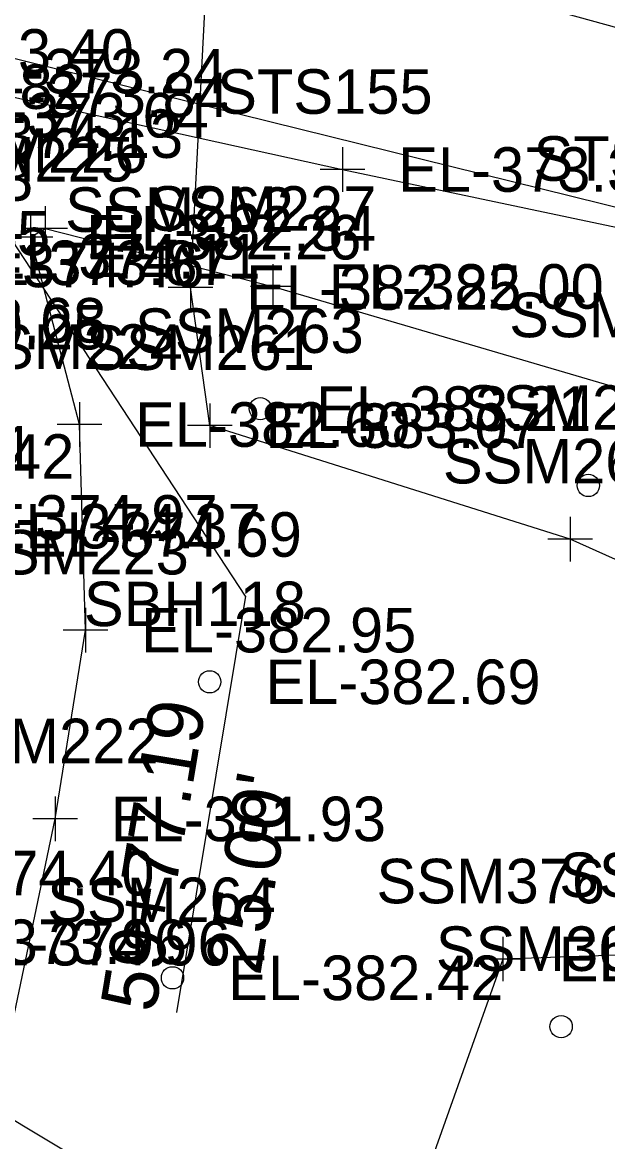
# Model space of a CAD drawing. Extents: x 1189978 to 1314812, y 571533 to 629339.
# Drawn here: x 1217620.1 to 1217672.6, y 621600.5 to 621701 of the extents above; entities that cross this region are included whole.
import ezdxf

# ---------------------------------------------------------------- set-up
doc = ezdxf.new("R2010")
doc.units = 0
for name, color, linetype in [('SURVEY - DRAINAGE - Bridge Hydraulic Data - Points - Elevations', 7, 'Continuous'), ('SURVEY - DRAINAGE - Bridge Hydraulic Data - Points - Numbers', 7, 'Continuous'), ('SURVEY - DRAINAGE - Bridge Hydraulic Data with Text', 7, 'Continuous'), ('SURVEY - DRAINAGE - Natural Features', 7, 'Continuous'), ('SURVEY - DRAINAGE - Pipes and Culverts', 7, 'Continuous'), ('SURVEY - DTM - Breaklines', 7, 'Continuous'), ('SURVEY - DTM - Breaklines - Points - Elevations', 7, 'Continuous'), ('SURVEY - DTM - Breaklines - Points - Locators', 7, 'Continuous'), ('SURVEY - DTM - Breaklines - Points - Numbers', 7, 'Continuous'), ('SURVEY - DTM - Spot Points - Elevations', 7, 'Continuous'), ('SURVEY - DTM - Spot Points - Locators', 7, 'Continuous'), ('SURVEY - DTM - Spot Points - Point Numbers', 7, 'Continuous'), ('SURVEY - PROPERTY - Property Lines', 7, 'Continuous'), ('SURVEY - PROPERTY - Station and Offset Flags', 7, 'Continuous'), ('SURVEY - VEGETATION - Features - Points - Elevations', 7, 'Continuous'), ('SURVEY - VEGETATION - Features - Points - Locators', 7, 'Continuous'), ('SURVEY - VEGETATION - Features - Points - Numbers', 7, 'Continuous'), ('SURVEY - VEGETATION - Features with Text', 7, 'Continuous')]:
    doc.layers.add(name, color=color, linetype=linetype)

msp = doc.modelspace()

# ---------------------------------------------------------------- linework, layer by layer
at = {"layer": 'SURVEY - DRAINAGE - Bridge Hydraulic Data with Text'}
for p, q in [((1217648.86, 621689.75), (1217648.86, 621685.75)), ((1217650.86, 621687.75), (1217646.86, 621687.75)), ((1217620.87, 621683.67), (1217620.87, 621679.67)), ((1217622.2, 621684.46), (1217622.2, 621680.46)), ((1217624.2, 621682.46), (1217620.2, 621682.46)), ((1217622.87, 621681.67), (1217618.87, 621681.67)), ((1217642.62, 621679.25), (1217642.62, 621675.25)), ((1217644.62, 621677.25), (1217640.62, 621677.25)), ((1217625.26, 621666.85), (1217625.26, 621662.85)), ((1217627.26, 621664.85), (1217623.26, 621664.85)), ((1217625.8, 621648.39), (1217625.8, 621644.39)), ((1217627.8, 621646.39), (1217623.8, 621646.39)), ((1217623.08, 621631.44), (1217623.08, 621627.44)), ((1217625.08, 621629.44), (1217621.08, 621629.44))]:
    msp.add_line(p, q, dxfattribs=at)
for points in [[(1217608.75, 621696.58), (1217648.86, 621687.75), (1217677.35, 621681.74), (1217732.6, 621657.47), (1217781.29, 621629.61), (1217836.19, 621612.25), (1217873.97, 621607.18), (1217947.65, 621606.21), (1218006.33, 621594.8), (1218055.31, 621583.64), (1218102.03, 621575.33), (1218143.8, 621568.44), (1218175.72, 621558.82)], [(1217620.87, 621681.67), (1217622.2, 621682.46), (1217642.62, 621677.25), (1217675.1, 621667.69), (1217729.16, 621644.15), (1217773.26, 621620.9), (1217815.41, 621607.07), (1217868.64, 621590.01), (1217924.4, 621592.51), (1217974.68, 621583.83), (1218029.18, 621580.33), (1218078.58, 621559.01), (1218129.76, 621551.77), (1218165.8, 621544.45)], [(1217505.54, 621026.79), (1217510.58, 621028.06), (1217516.48, 621028.53), (1217518.24, 621034.42), (1217525.77, 621071.02), (1217531.12, 621100.75), (1217543.76, 621178.47), (1217557.61, 621268.24), (1217565, 621315.17), (1217570.43, 621349.89), (1217572.63, 621390.62), (1217580.88, 621434.75), (1217592.39, 621481.3), (1217594.39, 621494.68), (1217597.98, 621511.62), (1217601.47, 621549.78), (1217613.22, 621582.3), (1217623.08, 621629.44), (1217625.8, 621646.39), (1217625.26, 621664.85), (1217620.87, 621681.67)]]:
    msp.add_lwpolyline(points, dxfattribs=at)
at = {"layer": 'SURVEY - DRAINAGE - Natural Features'}
msp.add_lwpolyline([(1217597.92, 621711.33), (1217604.68, 621710.65), (1217655.29, 621705.53), (1217679.89, 621698.73), (1217740.8, 621672.97), (1217788.76, 621648.92), (1217842.88, 621634.67), (1217893, 621624.41), (1217946.99, 621626.51), (1218003.43, 621612.97), (1218049.35, 621603.62), (1218106.32, 621591.17), (1218155.43, 621579.99), (1218184.56, 621577.09)], dxfattribs=at)
at = {"layer": 'SURVEY - DRAINAGE - Pipes and Culverts'}
msp.add_line((1217655.99, 621580.4), (1217606.77, 621609.94), dxfattribs=at)
at = {"layer": 'SURVEY - DTM - Breaklines'}
msp.add_lwpolyline([(1217652.9, 621587.7), (1217651.43, 621582.83), (1217643.26, 621546.04), (1217642.15, 621538.34), (1217648.55, 621531.36), (1217656.64, 621530.3), (1217674, 621546.86), (1217683.49, 621555.46), (1217690.06, 621576.59), (1217691.54, 621598.37), (1217679.54, 621617.42), (1217663.26, 621616.86), (1217652.9, 621587.7)], dxfattribs=at)
at = {"layer": 'SURVEY - DTM - Breaklines - Points - Locators'}
for p, q in [((1217663.26, 621618.86), (1217663.26, 621614.86)), ((1217665.26, 621616.86), (1217661.26, 621616.86))]:
    msp.add_line(p, q, dxfattribs=at)
at = {"layer": 'SURVEY - DTM - Spot Points - Locators'}
for centre in [(1217641.49, 621666.28), (1217670.92, 621659.38), (1217636.95, 621641.75), (1217633.61, 621615.17), (1217668.48, 621610.79)]:
    msp.add_circle(centre, 1, dxfattribs=at)
at = {"layer": 'SURVEY - PROPERTY - Property Lines'}
msp.add_line((1217606.4, 621700.95), (1218832.82, 621397.44), dxfattribs=at)
at = {"layer": 'SURVEY - PROPERTY - Station and Offset Flags'}
msp.add_line((1217640.15, 621649.45), (1217633.97, 621612.06), dxfattribs=at)
msp.add_lwpolyline([(1217640.15, 621649.45), (1217606.4, 621700.95)], dxfattribs=at)
at = {"layer": 'SURVEY - VEGETATION - Features - Points - Locators'}
for p, q in [((1217635.22, 621679.15), (1217635.22, 621675.15)), ((1217637.22, 621677.15), (1217633.22, 621677.15)), ((1217636.96, 621666.75), (1217636.96, 621662.75)), ((1217638.96, 621664.75), (1217634.96, 621664.75)), ((1217669.28, 621656.56), (1217669.28, 621652.56)), ((1217671.28, 621654.56), (1217667.28, 621654.56))]:
    msp.add_line(p, q, dxfattribs=at)
at = {"layer": 'SURVEY - VEGETATION - Features with Text'}
for points in [[(1217635.22, 621677.15), (1217638.44, 621739.02), (1217645.2, 621755.16), (1217657.66, 621755.11), (1217696.15, 621736.61), (1217739.97, 621716.31), (1217783.32, 621708.86), (1217822.96, 621695.3), (1217862.84, 621685.05), (1217908.72, 621679.47), (1217951.79, 621669.62), (1217991.8, 621657.05), (1218033.03, 621649.12), (1218078.72, 621641.96), (1218126.57, 621635.34), (1218178.05, 621621.05)], [(1218164.35, 621532.61), (1218126.36, 621537.58), (1218076.43, 621544.76), (1218024.24, 621555.32), (1217973.55, 621564.98), (1217919.77, 621572.71), (1217865.16, 621580.88), (1217811.45, 621595.34), (1217767.54, 621609.78), (1217723.9, 621630.04), (1217669.28, 621654.56), (1217636.96, 621664.75), (1217635.22, 621677.15)]]:
    msp.add_lwpolyline(points, dxfattribs=at)

# ---------------------------------------------------------------- texts
at = {"layer": 'SURVEY - DRAINAGE - Bridge Hydraulic Data - Points - Elevations'}
for s, p in [('EL-373.40', (1217605.47, 621696.35)), ('EL-373.24', (1217613.75, 621694.58)), ('EL-373.33', (1217653.86, 621685.75)), ('EL-382.34', (1217627.2, 621680.46)), ('EL-382.00', (1217647.62, 621675.25))]:
    msp.add_text(s, height=4, dxfattribs=at).set_placement(p)
at = {"layer": 'SURVEY - DRAINAGE - Bridge Hydraulic Data - Points - Numbers'}
for s, p in [('STS155', (1217637.62, 621692.75)), ('SSM226', (1217610.85, 621687.46)), ('STS156', (1217666, 621686.74)), ('SSM227', (1217631.38, 621682.25)), ('SSM228', (1217663.82, 621672.69))]:
    msp.add_text(s, height=4, dxfattribs=at).set_placement(p)
at = {"layer": 'SURVEY - DTM - Breaklines - Points - Elevations'}
for s, p in [('EL-373.84', (1217613.98, 621692.45)), ('EL-373.64', (1217612.18, 621690.62)), ('EL-374.13', (1217609.88, 621688.79)), ('EL-382.26', (1217625.87, 621679.67)), ('EL-374.11', (1217616.84, 621677.95)), ('EL-374.46', (1217611.79, 621677.18)), ('EL-373.87', (1217614.15, 621677.37)), ('EL-379.25', (1217602.98, 621671.59)), ('EL-378.68', (1217602.99, 621672.21)), ('EL-382.60', (1217630.26, 621662.85)), ('EL-374.97', (1217612.97, 621654.51)), ('EL-374.37', (1217616.84, 621653.72)), ('EL-374.69', (1217620.53, 621652.98)), ('EL-382.95', (1217630.8, 621644.39)), ('EL-381.93', (1217628.08, 621627.44)), ('EL-374.40', (1217607.31, 621622.58)), ('EL-373.96', (1217610.23, 621616.41)), ('EL-374.96', (1217614.15, 621616.28)), ('EL-382.28', (1217668.26, 621614.86))]:
    msp.add_text(s, height=4, dxfattribs=at).set_placement(p)
at = {"layer": 'SURVEY - DTM - Breaklines - Points - Numbers'}
for s, p in [('SSM225', (1217609.63, 621686.67)), ('SSM343', (1217600.6, 621684.95)), ('SSM224', (1217614.02, 621669.85)), ('SSM341', (1217600.76, 621660.72)), ('SSM342', (1217604.29, 621659.98)), ('SSM223', (1217614.56, 621651.39)), ('SSM222', (1217611.84, 621634.44)), ('SSM375', (1217668.3, 621622.42)), ('SSM376', (1217651.91, 621621.86))]:
    msp.add_text(s, height=4, dxfattribs=at).set_placement(p)
at = {"layer": 'SURVEY - DTM - Spot Points - Elevations'}
for s, p in [('EL-374.82', (1217601.15, 621693.19)), ('EL-377.45', (1217597.95, 621680.03)), ('EL-383.21', (1217646.49, 621664.28)), ('EL-382.69', (1217641.95, 621639.75)), ('EL-382.42', (1217638.61, 621613.17))]:
    msp.add_text(s, height=4, dxfattribs=at).set_placement(p)
at = {"layer": 'SURVEY - DTM - Spot Points - Point Numbers'}
for s, p in [('SSM263', (1217630.25, 621671.28)), ('SSM259', (1217659.66, 621664.38)), ('SBH118', (1217625.66, 621646.75)), ('SSM264', (1217622.37, 621620.17)), ('SSM364', (1217657.24, 621615.79))]:
    msp.add_text(s, height=4, dxfattribs=at).set_placement(p)
at = {"layer": 'SURVEY - PROPERTY - Station and Offset Flags'}
for s, p in [('59+77.19', (1217632.05, 621611.94)), ("25.00'", (1217641.47, 621615.27))]:
    msp.add_text(s, height=5, rotation=80.6236, dxfattribs=at).set_placement(p)
at = {"layer": 'SURVEY - VEGETATION - Features - Points - Elevations'}
for s, p in [('EL-382.25', (1217640.22, 621675.15)), ('EL-383.07', (1217641.96, 621662.75))]:
    msp.add_text(s, height=4, dxfattribs=at).set_placement(p)
at = {"layer": 'SURVEY - VEGETATION - Features - Points - Numbers'}
for s, p in [('SSM262', (1217623.98, 621682.15)), ('SSM261', (1217625.88, 621669.75)), ('SSM260', (1217657.87, 621659.56))]:
    msp.add_text(s, height=4, dxfattribs=at).set_placement(p)

doc.saveas('drawing.dxf')
